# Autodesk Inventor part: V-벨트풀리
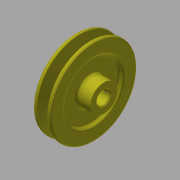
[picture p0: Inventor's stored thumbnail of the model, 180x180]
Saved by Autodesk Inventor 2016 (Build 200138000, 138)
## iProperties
Created: 2015-09
Part Number: V-벨트풀리
Material: 강철, 연강
Document SubType Name: Modeling
Designer: mduedu
Density: 7.86 g/cm^3
Mass: 779.014 g
Surface Area: 277.465 cm^2
Volume: 99.1112 cm^3
Appearance: 강철
Author: mduedu
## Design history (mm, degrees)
sketch "스케치1"
  geometry: L1 (-10, 0)-(10, 0); L2 (-10, 0)-(-10, 48); L3 (-10, 48)-(-5.976, 48); L4 (-5.976, 48)-(-2.154, 35.5); L5 (-2.154, 35.5)-(2.154, 35.5); L6 (2.154, 35.5)-(5.976, 48); L7 (5.976, 48)-(10, 48); L8 (10, 48)-(10, 0); L9 (0, 0)-(0, 35.5); L10 (-10, 43.5)-(10, 43.5); 3 further points
  constraints: 20 end point, 6 point on line, 3 perpendicular, 2 midpoint, 2 parallel, 2 symmetric about line, 1 coincident, 1 collinear, 1 equal length, 1 horizontal, 1 vertical, 1 vertical alignment
  dimensions: "d0" = 20 distance between parallel lines of L8 L2; "d2" = 96 diameter of L3 L1; "d3" = 87 diameter of L10 L1; "d4" = 4.5 distance between parallel lines of L10 L3 (derived); "d5" = 8 distance between parallel lines of L5 L10; "d6" = 9.2 distance of point (4.6, 43.5) point (-4.6, 43.5); "d7" = 34 deg angle of L6 L4
revolve "회전1" sketch "스케치1" stored, may be unused: angle "d8" = 90 deg
sketch "스케치2"
  geometry: C1 r 15 at (0, 0); 1 further point
  constraints: 1 centre point, 1 coincident
  dimensions: "d9" = 30 diameter of C1
extrude "돌출1" join sketch "스케치2" distance "d10" = 11; taper "d11" = 0 deg
fillet "모깎기1" dims "d12" = 1, "d13" = 0.5, "d14" = 2
sketch "스케치3"
  geometry: C1 r 15 at (0, 0) reference; C2 r 32 at (0, 0); 1 further point
  constraints: 1 centre point, 1 coincident
  dimensions: "d15" = 64 diameter of C2
extrude "돌출2" cut sketch "스케치3" distance "d16" = 4; taper "d17" = 0 deg
fillet "모깎기2" dims "d18" = 3
fillet "모깎기3" dims "d19" = 3
fillet "모깎기4" dims "d20" = 3
sketch "스케치4"
  geometry: C1 r 7.5 at (0, 0); 1 further point
  constraints: 1 centre point, 1 coincident
  dimensions: "d21" = 15 diameter of C1
extrude "돌출3" cut sketch "스케치4" stored distance "d22" = 4; taper "d23" = 0 deg
sketch "스케치5"
  geometry: L1 (-2.5, 7.071)-(2.5, 7.071); L2 (2.5, 7.071)-(2.5, 9.8); L3 (2.5, 9.8)-(-2.5, 9.8); L4 (-2.5, 9.8)-(-2.5, 7.071); A1 r 7.5 centre (0, 0) between (-2.5, 7.071) and (2.5, 7.071) reference; 2 further points
  constraints: 8 end point, 3 point on circle, 2 parallel, 1 horizontal, 1 perpendicular, 1 vertical alignment
  dimensions: "d24" = 5 distance of L2.end L3.end; "d26" = 17.3 distance from line of L3 point (0, -7.5)
extrude "돌출4" cut sketch "스케치5" stored distance "d27" = 4; taper "d28" = 0 deg
chamfer "모따기1" distance "d29" = 1; stored, may be unused: second distance "d30" = 2, angle "d31" = 45 deg
node "작업 평면1"
sketch "스케치6"
  geometry: L1 (-11, 15)-(-11, -15) reference; 2 further points
  constraints: 1 horizontal alignment
  dimensions: "d32" = 5 distance from line of point (-6, 0) L1
hole "구멍1" sketch "스케치6" at (-6, 0) diameter "d33" = 3.242; stored, may be unused: countersink angle "d37" = 90 deg, drill point angle "d39" = 118 deg; dims "d34" = 6, "d35" = 4, "d36" = 2, "d38" = 8
node "솔리드1"
mirror "대칭1"
